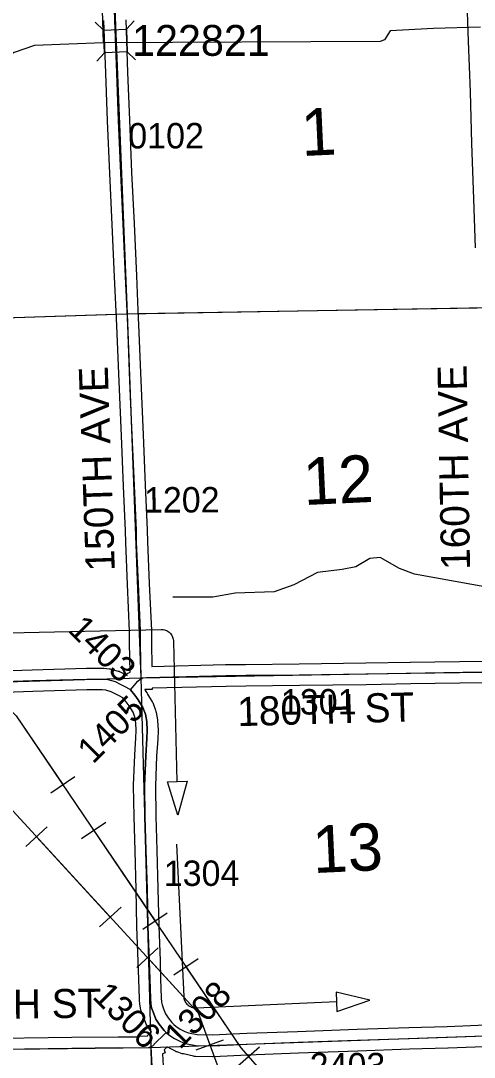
# Model space of a CAD drawing. Extents: x 128.7 to 185.5, y -21.4 to 12.6.
# Drawn here: x 138.733 to 139.982, y -4.606 to -1.752 of the extents above; entities that cross this region are included whole.
import ezdxf

# ---------------------------------------------------------------- set-up
doc = ezdxf.new("R2010")
doc.units = 0
for name, color, linetype in [('tdCoDirctArrow', 7, 'Continuous'), ('tdCoHydroRiver', 7, 'Continuous'), ('tdCoPipe', 7, 'Continuous'), ('tdCoSecRdNmbr', 7, 'Continuous'), ('tdCoSecRdTxt', 7, 'Continuous'), ('tdCoSecRteBand', 7, 'Continuous'), ('tdCoSecRteCL', 7, 'Continuous'), ('tdCoSectLine', 7, 'Continuous'), ('tdCoSectLinePart', 7, 'Continuous'), ('tdCoSectNmbr', 7, 'Continuous'), ('tdCoStrucSec', 7, 'Continuous'), ('tdCoStrucSecFHWANum', 7, 'Continuous'), ('tdCoSurfAsphalt', 7, 'Continuous'), ('tdCoSurfGravel', 7, 'Continuous')]:
    doc.layers.add(name, color=color, linetype=linetype)

msp = doc.modelspace()

# ---------------------------------------------------------------- linework, layer by layer
at = {"layer": 'tdCoDirctArrow'}
for points in [[(138.7007, -3.4377), (139.12, -3.4278), (139.1236, -3.4279), (139.1258, -3.4282), (139.1287, -3.4288), (139.1315, -3.4296), (139.1342, -3.4307), (139.1368, -3.432), (139.1393, -3.4336), (139.1416, -3.4353), (139.1438, -3.4373), (139.1458, -3.4394), (139.1475, -3.4417), (139.1491, -3.4442), (139.1505, -3.4468), (139.1516, -3.4495), (139.1525, -3.4523), (139.1531, -3.4551), (139.1535, -3.458), (139.1536, -3.4609), (139.1633, -3.8466)], [(139.1626, -4.0194), (139.1819, -4.4384), (139.1823, -4.4419), (139.1828, -4.4441), (139.1836, -4.447), (139.1846, -4.4497), (139.1859, -4.4523), (139.1874, -4.4548), (139.1891, -4.4572), (139.191, -4.4594), (139.1931, -4.4614), (139.1954, -4.4632), (139.1978, -4.4649), (139.2004, -4.4663), (139.203, -4.4674), (139.2058, -4.4684), (139.2086, -4.4691), (139.2115, -4.4695), (139.2144, -4.4697), (139.2174, -4.4696), (139.6028, -4.4524)]]:
    msp.add_lwpolyline(points, dxfattribs=at)
for points in [[(139.1911, -3.8457), (139.1659, -3.9388), (139.1372, -3.8475)], [(139.6038, -4.4801), (139.6949, -4.4486), (139.6018, -4.4263)]]:
    msp.add_lwpolyline(points, close=True, dxfattribs=at)
at = {"layer": 'tdCoHydroRiver'}
for points in [[(139.6382, -0.4711), (139.6108, -0.5019), (139.5984, -0.5102), (139.5618, -0.5508), (139.5442, -0.5924), (139.5261, -0.6718), (139.513, -0.7069), (139.504, -0.7198), (139.4936, -0.7407), (139.4601, -0.7796), (139.4119, -0.8048), (139.3842, -0.8277), (139.2943, -0.93), (139.256, -0.9659), (139.2064, -0.9927), (139.1578, -1.0037), (139.0791, -1.0109), (139.0511, -1.0228), (138.9978, -1.0355), (138.9604, -1.0509), (138.9374, -1.0721), (138.954, -1.6034), (138.9606, -1.813)], [(139.9991, -1.7695), (139.8699, -1.7735), (139.7502, -1.7804), (139.7351, -1.8046), (139.7227, -1.8097), (138.9606, -1.813), (138.7715, -1.8205), (138.7152, -1.8396), (138.6594, -1.8714), (138.5693, -1.9673), (138.5197, -2.0446), (138.5034, -2.0798), (138.4943, -2.0927), (138.4824, -2.1136), (138.452, -2.1524), (138.4349, -2.1609)], [(140.0872, -3.3242), (139.8174, -3.2759), (139.7759, -3.2598), (139.7229, -3.2299), (139.6946, -3.2324), (139.6559, -3.2557), (139.6182, -3.2632), (139.5506, -3.2716), (139.4854, -3.3052), (139.4308, -3.3243), (139.3236, -3.3276), (139.2624, -3.339), (139.1519, -3.3393)]]:
    msp.add_lwpolyline(points, dxfattribs=at)
at = {"layer": 'tdCoPipe'}
for p, q in [((138.8158, -3.8777), (138.8825, -3.8325)), ((138.901, -4.0037), (138.9676, -3.9586)), ((138.7473, -4.0259), (138.8064, -3.9717)), ((138.9502, -4.2469), (139.0094, -4.1925)), ((139.0697, -4.2531), (139.1365, -4.2079)), ((139.0527, -4.3585), (139.1117, -4.3042)), ((139.1549, -4.3791), (139.2216, -4.334)), ((139.2164, -4.5851), (139.2918, -4.5574)), ((139.3299, -4.6301), (139.3905, -4.5769))]:
    msp.add_line(p, q, dxfattribs=at)
for points in [[(133.5703, 0.7502), (134.415, 0.1836), (134.5616, 0.095), (136.3082, -1.518), (137.2828, -2.2589), (137.4566, -2.6804), (137.8852, -3.0711), (138.1505, -3.1526), (138.4929, -3.4522), (138.721, -3.6658), (139.3396, -4.5801), (139.8377, -5.1477), (140.0414, -5.3544), (140.3867, -5.5234), (140.8191, -5.9061), (141.5748, -6.8225), (141.7836, -7.0033), (142.3273, -7.8596)], [(133.6945, 0.4089), (135.1153, -0.6342), (137.1324, -2.3792), (137.5288, -2.9528), (138.161, -3.328), (139.2218, -4.4833), (139.3397, -4.805), (140.8827, -6.1264), (141.2631, -6.6089), (142.2971, -8.0348), (142.3319, -8.2734), (143.9392, -9.367), (143.9927, -9.5975), (145.829, -10.533), (147.4283, -11.2406), (148.0149, -11.3532), (148.9915, -11.5772), (150.6773, -11.7094), (151.6631, -11.8649), (152.1578, -12.9549), (152.0489, -14.0003)], [(138.6681, -3.6162), (138.721, -3.6658), (138.8491, -3.8551)], [(138.9344, -3.9811), (139.1031, -4.2305)], [(138.7769, -3.9987), (138.9798, -4.2197)], [(139.0823, -4.3313), (139.2218, -4.4833), (139.2541, -4.5712)], [(139.1883, -4.3565), (139.3396, -4.5801), (139.3602, -4.6035)]]:
    msp.add_lwpolyline(points, dxfattribs=at)
at = {"layer": 'tdCoSecRteBand'}
for points in [[(139.9851, -2.3771), (139.9807, -2.2424), (139.9755, -2.0903), (139.9755, -2.0902), (139.9755, -2.0901), (139.9715, -1.9482), (139.9661, -1.8088), (139.9661, -1.8087), (139.9661, -1.8087), (139.9614, -1.6738)], [(138.4532, -3.5495), (138.7646, -3.5389), (138.7647, -3.5389), (138.7648, -3.5389), (138.914, -3.5344), (138.9144, -3.5344), (138.9149, -3.5344), (138.9592, -3.5344), (138.9608, -3.5344), (138.9623, -3.5346), (138.9766, -3.536), (138.9791, -3.5363), (138.9815, -3.537), (139.0012, -3.5424), (139.0042, -3.5432), (139.0069, -3.5446), (139.0209, -3.5517), (139.021, -3.5517), (139.021, -3.5518), (139.0265, -3.5546), (139.0244, -3.5503), (139.0343, -3.5454), (139.033, -3.4661), (139.033, -3.4659), (139.033, -3.4656), (139.033, -3.4328), (139.0273, -3.304), (139.0273, -3.3039), (139.0273, -3.3039), (139.0224, -3.1888), (139.0224, -3.1885), (139.0224, -3.1882), (139.0217, -3.1564), (139.0162, -3.0334), (139.0162, -3.0334), (139.0162, -3.0334), (139.0103, -2.8945), (139.0103, -2.8945), (139.0103, -2.8945), (139.0042, -2.7451), (138.9978, -2.5917), (138.996, -2.5526), (138.9918, -2.4574), (138.9854, -2.3129), (138.9785, -2.1729), (138.9785, -2.1728), (138.9785, -2.1727), (138.9724, -2.0277), (138.9723, -2.0277), (138.9723, -2.0276), (138.9674, -1.8969), (138.9674, -1.8968), (138.9674, -1.8968), (138.9622, -1.7513)], [(139.0222, -1.7493), (139.0274, -1.8946), (139.0323, -2.0252), (139.0385, -2.1701), (139.0454, -2.31), (139.0454, -2.3101), (139.0454, -2.3102), (139.0518, -2.4547), (139.0518, -2.4547), (139.0518, -2.4547), (139.056, -2.55), (139.0577, -2.5891), (139.0577, -2.5892), (139.0577, -2.5892), (139.0641, -2.7426), (139.0641, -2.7426), (139.0641, -2.7426), (139.0703, -2.892), (139.0762, -3.0308), (139.0816, -3.1541), (139.0816, -3.1544), (139.0816, -3.1547), (139.0824, -3.1865), (139.0873, -3.3013), (139.093, -3.4308), (139.093, -3.4314), (139.093, -3.4321), (139.093, -3.4654), (139.0941, -3.5298)], [(139.0941, -3.5298), (139.2975, -3.5247), (139.2977, -3.5247), (139.2979, -3.5247), (139.3524, -3.524), (139.3524, -3.524), (139.3525, -3.524), (139.4999, -3.5225), (139.6833, -3.5203), (139.806, -3.5181), (139.806, -3.5181), (139.8061, -3.5181), (140.0082, -3.5151)], [(138.6113, -4.5545), (138.8737, -4.5508), (138.8737, -4.5508), (138.8737, -4.5508), (139.0014, -4.5491), (139.0017, -4.5491), (139.002, -4.5491), (139.0597, -4.5494), (139.0607, -4.5493), (139.0607, -4.5478), (139.0819, -4.5467), (139.0831, -4.5454), (139.0834, -4.5452), (139.0836, -4.545), (139.0931, -4.5356), (139.0909, -4.5327), (139.0902, -4.5318), (139.0896, -4.5309), (139.0805, -4.5171), (139.0787, -4.5144), (139.0775, -4.5115), (139.0709, -4.4944), (139.0708, -4.4943), (139.0708, -4.4942), (139.0656, -4.4806), (139.0647, -4.4782), (139.0642, -4.4757), (139.062, -4.4644), (139.0617, -4.4628), (139.0615, -4.4612), (139.0603, -4.4469), (139.0602, -4.4461), (139.0602, -4.4453), (139.0585, -4.3918), (139.0585, -4.3917), (139.0585, -4.3917), (139.057, -4.342), (139.0533, -4.2457), (139.0533, -4.2454), (139.0533, -4.2452), (139.0511, -4.1437), (139.0481, -4.0373), (139.0454, -3.9431), (139.0454, -3.9429), (139.0454, -3.9426), (139.0442, -3.8586), (139.0442, -3.8578), (139.0442, -3.8569), (139.0474, -3.7743), (139.0474, -3.7739), (139.0474, -3.7735), (139.0506, -3.7262), (139.0515, -3.706), (139.0502, -3.685), (139.0476, -3.6693), (139.0424, -3.6557), (139.0318, -3.6379), (139.024, -3.6272), (139.0145, -3.6162), (139.0039, -3.6104), (138.9937, -3.6052), (138.9824, -3.5994), (138.968, -3.5955), (138.9577, -3.5944), (138.9153, -3.5944), (138.7666, -3.5988), (138.4552, -3.6094)], [(140.0092, -3.5751), (139.807, -3.578), (139.6843, -3.5803), (139.6842, -3.5803), (139.6841, -3.5803), (139.5006, -3.5825), (139.5006, -3.5825), (139.5005, -3.5825), (139.3531, -3.584), (139.2988, -3.5847), (139.0951, -3.5898), (139.0951, -3.5932), (139.0751, -3.5936), (139.0747, -3.5941), (139.0776, -3.5975), (139.077, -3.598), (139.0811, -3.6037), (139.082, -3.6048), (139.0827, -3.6061), (139.0953, -3.6273), (139.0966, -3.6295), (139.0975, -3.6319), (139.1047, -3.6506), (139.1057, -3.6534), (139.1062, -3.6563), (139.1097, -3.6765), (139.1099, -3.6781), (139.11, -3.6797), (139.1115, -3.7039), (139.1116, -3.7055), (139.1115, -3.707), (139.1105, -3.7292), (139.1105, -3.7296), (139.1105, -3.7299), (139.1073, -3.7771), (139.1042, -3.8585), (139.1054, -3.9416), (139.1081, -4.0355), (139.1081, -4.0356), (139.1081, -4.0356), (139.1111, -4.1421), (139.1111, -4.1422), (139.1111, -4.1423), (139.1133, -4.2436), (139.117, -4.3398), (139.117, -4.3399), (139.117, -4.3401), (139.1185, -4.3899), (139.1202, -4.4425), (139.1212, -4.4544), (139.1226, -4.4617), (139.1268, -4.4727), (139.1323, -4.4866), (139.139, -4.4969), (139.1493, -4.5102), (139.1545, -4.5153), (139.16, -4.5202), (139.1723, -4.5284), (139.1848, -4.5349), (139.1951, -4.5383), (139.2189, -4.5433), (139.2614, -4.5442)], [(139.2614, -4.5442), (139.3555, -4.5396), (139.3557, -4.5396), (139.3559, -4.5396), (139.4957, -4.5344), (139.4958, -4.5344), (139.4958, -4.5344), (139.6593, -4.5287), (139.8016, -4.5238), (139.8017, -4.5238), (139.8017, -4.5238), (139.9077, -4.5206), (140.0572, -4.5149)], [(140.0593, -4.5748), (139.9098, -4.5806), (139.9097, -4.5806), (139.9096, -4.5806), (139.8036, -4.5838), (139.6614, -4.5887), (139.4979, -4.5944), (139.3583, -4.5995), (139.2633, -4.6042), (139.2623, -4.6043), (139.2612, -4.6043), (139.2148, -4.6033), (139.212, -4.6032), (139.2093, -4.6026), (139.1812, -4.5967), (139.1796, -4.5964), (139.178, -4.5959), (139.1637, -4.5912), (139.1614, -4.5904), (139.1591, -4.5893), (139.1431, -4.5809), (139.1417, -4.5801), (139.1404, -4.5792), (139.1378, -4.5775), (139.136, -4.5795), (139.135, -4.5785), (139.1279, -4.5855), (139.131, -4.5934), (139.1233, -4.5964), (139.125, -4.6297)]]:
    msp.add_lwpolyline(points, dxfattribs=at)
at = {"layer": 'tdCoSecRteCL'}
for points in [[(139.0646, -3.5638), (139.063, -3.4656), (139.063, -3.4321), (139.0573, -3.3026), (139.0524, -3.1875), (139.0516, -3.1554), (139.0462, -3.0321), (139.0403, -2.8933), (139.0341, -2.7438), (139.0277, -2.5904), (139.026, -2.5513), (139.0218, -2.456), (139.0154, -2.3115), (139.0085, -2.1715), (139.0023, -2.0264), (138.9974, -1.8957), (138.9922, -1.7502), (138.9885, -1.6277), (138.9863, -1.5598)], [(138.0445, -3.5917), (138.0806, -3.5908), (138.2234, -3.5859), (138.308, -3.5839), (138.4542, -3.5794), (138.7657, -3.5688), (138.9149, -3.5644), (138.9592, -3.5644), (138.9735, -3.5659), (138.9933, -3.5713), (139.0073, -3.5785), (139.0179, -3.5839), (139.0337, -3.5925), (139.0353, -3.5943)], [(139.0353, -3.5943), (139.0554, -3.5705), (139.062, -3.5651), (139.0645, -3.5638), (139.0646, -3.5638)], [(139.0646, -3.5638), (139.0694, -3.5614), (139.0795, -3.5601), (139.2983, -3.5547), (139.3528, -3.554), (139.5002, -3.5525), (139.6837, -3.5503), (139.8065, -3.548), (140.0087, -3.5451), (140.0558, -3.5439)], [(139.134, -4.5371), (139.1282, -4.5318), (139.1146, -4.5143), (139.1055, -4.5005), (139.0988, -4.4835), (139.0936, -4.4699), (139.0914, -4.4586), (139.0902, -4.4443), (139.0885, -4.3908), (139.087, -4.341), (139.0833, -4.2445), (139.0811, -4.1429), (139.0781, -4.0364), (139.0754, -3.9422), (139.0742, -3.8581), (139.0774, -3.7755), (139.0806, -3.7279), (139.0816, -3.7057), (139.0801, -3.6815), (139.0766, -3.6613), (139.0695, -3.6426), (139.0569, -3.6214), (139.0475, -3.6085), (139.0353, -3.5943)], [(139.0922, -4.5762), (139.0968, -4.5744), (139.1047, -4.5663), (139.1276, -4.5436), (139.134, -4.5371)], [(139.134, -4.5371), (139.1415, -4.5439), (139.157, -4.5543), (139.1731, -4.5627), (139.1874, -4.5674), (139.2155, -4.5733), (139.2618, -4.5743), (139.357, -4.5696), (139.4968, -4.5644), (139.6603, -4.5587), (139.8026, -4.5538), (139.9087, -4.5506), (140.0883, -4.5437)], [(137.1591, -4.6049), (137.1792, -4.6048), (137.3217, -4.6023), (137.4307, -4.6011), (137.5481, -4.5986), (137.6532, -4.5979), (137.736, -4.5966), (137.8879, -4.5937), (138.066, -4.5912), (138.1681, -4.5897), (138.371, -4.588), (138.5, -4.586), (138.6117, -4.5845), (138.8741, -4.5808), (139.0018, -4.5791), (139.06, -4.5794), (139.0859, -4.5786), (139.0922, -4.5762)], [(139.1159, -5.8313), (139.1143, -5.7602), (139.1145, -5.7104), (139.1123, -5.6204), (139.1106, -5.5489), (139.1096, -5.5094), (139.1079, -5.4512), (139.1071, -5.4085), (139.1067, -5.3538), (139.1044, -5.2628), (139.1047, -5.1782), (139.1052, -5.0968), (139.1054, -5.0391), (139.1042, -4.9918), (139.0995, -4.8872), (139.0978, -4.8182), (139.097, -4.7516), (139.0963, -4.6889), (139.0951, -4.6312), (139.0922, -4.5762)]]:
    msp.add_lwpolyline(points, dxfattribs=at)
at = {"layer": 'tdCoSectLine'}
for points in [[(138.9859, -1.5598), (139.0261, -2.559)], [(138.0106, -2.5918), (139.0261, -2.559)], [(139.0261, -2.559), (140.02, -2.5417)], [(139.0261, -2.559), (139.0641, -3.5611)], [(138.0441, -3.5917), (139.0641, -3.5611)], [(139.0641, -3.5611), (140.0555, -3.5439)], [(139.0641, -3.5611), (139.0919, -4.5787)], [(139.0919, -4.5787), (140.0879, -4.5437)], [(138.0965, -4.5907), (139.0919, -4.5787)], [(139.0919, -4.5787), (139.1109, -5.5779)]]:
    msp.add_lwpolyline(points, dxfattribs=at)
at = {"layer": 'tdCoSectLinePart'}
for points in [[(138.0406, -2.5908), (138.9961, -2.56)], [(139.0561, -2.5585), (139.9897, -2.5423)], [(139.0907, -4.5324), (139.0908, -4.5375)], [(139.1359, -4.5772), (139.137, -4.5771)]]:
    msp.add_lwpolyline(points, dxfattribs=at)
at = {"layer": 'tdCoStrucSec'}
for p, q in [((138.9615, -1.7778), (138.9386, -1.7564)), ((139.0241, -1.7755), (139.0454, -1.7526)), ((138.9637, -1.8403), (138.9424, -1.8632)), ((139.0263, -1.8381), (139.0492, -1.8594))]:
    msp.add_line(p, q, dxfattribs=at)
msp.add_lwpolyline([(138.9637, -1.8403), (138.9615, -1.7778), (139.0241, -1.7755), (139.0263, -1.8381)], close=True, dxfattribs=at)
at = {"layer": 'tdCoSurfAsphalt'}
msp.add_lwpolyline([(138.4542, -3.5794), (138.7657, -3.5688), (138.9149, -3.5644), (138.9592, -3.5644), (138.9735, -3.5659), (138.9933, -3.5713), (139.0073, -3.5785), (139.0179, -3.5839), (139.0337, -3.5925), (139.0353, -3.5943), (139.0475, -3.6085), (139.0569, -3.6214), (139.0695, -3.6426), (139.0766, -3.6613), (139.0801, -3.6815), (139.0816, -3.7057), (139.0806, -3.7279), (139.0774, -3.7755), (139.0742, -3.8581), (139.0754, -3.9422), (139.0781, -4.0364), (139.0811, -4.1429), (139.0833, -4.2445), (139.087, -4.341), (139.0885, -4.3908), (139.0902, -4.4443), (139.0914, -4.4586), (139.0936, -4.4699), (139.0988, -4.4835), (139.1055, -4.5005), (139.1146, -4.5143), (139.1282, -4.5318), (139.134, -4.5371), (139.1415, -4.5439), (139.157, -4.5543), (139.1731, -4.5627), (139.1874, -4.5674), (139.2155, -4.5733), (139.2618, -4.5743), (139.357, -4.5696), (139.4968, -4.5644), (139.6603, -4.5587), (139.8026, -4.5538), (139.9087, -4.5506), (140.0883, -4.5437)], dxfattribs=at)
at = {"layer": 'tdCoSurfGravel'}
for points in [[(139.026, -2.5513), (139.0218, -2.456), (139.0154, -2.3115), (139.0085, -2.1715), (139.0023, -2.0264), (138.9974, -1.8957), (138.9922, -1.7502), (138.9885, -1.6277), (138.9863, -1.5598)], [(139.0646, -3.5638), (139.063, -3.4656), (139.063, -3.4321), (139.0573, -3.3026), (139.0524, -3.1875), (139.0516, -3.1554), (139.0462, -3.0321), (139.0403, -2.8933), (139.0341, -2.7438), (139.0277, -2.5904), (139.026, -2.5513)], [(139.0645, -3.5638), (139.0646, -3.5638), (139.0694, -3.5614), (139.0795, -3.5601), (139.2983, -3.5547), (139.3528, -3.554), (139.5002, -3.5525), (139.6837, -3.5503), (139.8065, -3.548), (140.0087, -3.5451), (140.0558, -3.5439), (140.1002, -3.5429), (140.3463, -3.5345), (140.5172, -3.53), (140.6815, -3.5251), (140.843, -3.5202), (141.0643, -3.5117)], [(139.0353, -3.5943), (139.0554, -3.5705), (139.062, -3.5651), (139.0645, -3.5638)], [(137.1591, -4.6049), (137.1792, -4.6048), (137.3217, -4.6023), (137.4307, -4.6011), (137.5481, -4.5986), (137.6532, -4.5979), (137.736, -4.5966), (137.8879, -4.5937), (138.066, -4.5912), (138.1681, -4.5897), (138.371, -4.588), (138.5, -4.586), (138.6117, -4.5845), (138.8741, -4.5808), (139.0018, -4.5791), (139.06, -4.5794), (139.0859, -4.5786), (139.0922, -4.5762), (139.0968, -4.5744), (139.1047, -4.5663), (139.1276, -4.5436), (139.134, -4.5371)], [(139.1159, -5.8313), (139.1143, -5.7602), (139.1145, -5.7104), (139.1123, -5.6204), (139.1106, -5.5489), (139.1096, -5.5094), (139.1079, -5.4512), (139.1071, -5.4085), (139.1067, -5.3538), (139.1044, -5.2628), (139.1047, -5.1782), (139.1052, -5.0968), (139.1054, -5.0391), (139.1042, -4.9918), (139.0995, -4.8872), (139.0978, -4.8182), (139.097, -4.7516), (139.0963, -4.6889), (139.0951, -4.6312), (139.0922, -4.5762)]]:
    msp.add_lwpolyline(points, dxfattribs=at)

# ---------------------------------------------------------------- texts
at = {"layer": 'tdCoSecRdNmbr'}
for s, rotation, p in [('0102', 0.106, (139.0294, -2.1039)), ('1202', 0.106, (139.0726, -3.1062)), ('1403', 315.1054, (138.8602, -3.4318)), ('1301', 0.1063, (139.4497, -3.6623)), ('1405', 45.1042, (138.9323, -3.8003)), ('1304', 0.106, (139.1272, -4.1342)), ('1306', 315.1054, (138.9278, -4.4411)), ('1308', 45.1043, (139.1713, -4.5863)), ('2403', 0.1063, (139.529, -4.664))]:
    msp.add_text(s, height=0.07, rotation=rotation, dxfattribs=at).set_placement(p)
at = {"layer": 'tdCoSecRdTxt'}
for s, rotation, p in [('150TH AVE', 92, (138.9925, -3.2669)), ('160TH AVE', 91, (139.9707, -3.2636)), ('180TH ST', 1.5938, (139.3305, -3.6943)), ('190TH ST', 0.6801, (138.4682, -4.5023))]:
    msp.add_text(s, height=0.08, rotation=rotation, dxfattribs=at).set_placement(p)
at = {"layer": 'tdCoSectNmbr'}
for s, rotation, p in [('1', 2.6587, (139.508, -2.1248)), ('12', 2.6587, (139.5137, -3.0856)), ('13', 2.6586, (139.5394, -4.0988))]:
    msp.add_text(s, height=0.13, rotation=rotation, dxfattribs=at).set_placement(p)
at = {"layer": 'tdCoStrucSecFHWANum'}
msp.add_text('122821', height=0.085, dxfattribs=at).set_placement((139.0398, -1.8488))

doc.saveas('drawing.dxf')
